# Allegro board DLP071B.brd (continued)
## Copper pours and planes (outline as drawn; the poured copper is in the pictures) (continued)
SWNODE_P3P3V on TOP (solid shape): 160.26,56.39 160.28,56.29 160.31,56.2 160.31,55.63 160.37,55.48 160.52,55.42 160.78,55.42 160.78,53.85 160.4,53.47 160.4,52.54 160.14,52.1 160.4,51.65 160.4,43.05 154.18,43.05 154.18,51.69 156.32,51.69 156.33,51.66 156.52,51.44 156.8,51.36 157.16,51.5 157.3,51.86 157.3,51.92 157.29,52 159.89,54.61 159.89,55.46 159.95,55.54 159.97,55.63 159.97,56.2 160.01,56.29 160.02,56.39 160.02,57.19 160.11,57.28 160.26,57.28
SWNODE_P5V on TOP (solid shape): 157.87,78.46 157.97,78.45 158.06,78.46 158.17,78.49 163.45,78.49 163.45,74.96 162.57,74.08 162.56,74.08 162.28,73.9 162.18,73.59 162.21,73.42 162.29,73.27 162.31,73.25 162.31,73.18 161.93,73.18 161.78,73.12 161.72,72.97 161.72,72.44 158.7,69.42 158.61,69.42 158.47,69.36 158.41,69.22 158.41,69.13 158.38,69.1 158.38,66.24 158.01,66.24 157.87,66.18 157.81,66.04 157.81,65.47 157.77,65.38 157.76,65.28 157.76,64.39 157.57,64.39 157.5,64.42 157.47,64.5 157.47,64.52 157.47,65.16 157.49,65.22 157.49,65.28 157.49,66.07 157.48,66.18 157.43,66.27 157.43,70.49 157.47,70.5 157.86,71 157.47,71.49 157.43,71.5 157.43,78.49 157.77,78.49
N16830232 on TOP (solid shape): outline of 315 points within 138.31,50.38 156.34,62.36
N16830232 on BOTTOM: 149.22,65.02 152.4,65.02 152.53,64.9 152.53,62.1 151.38,60.96 149.86,60.96 149.73,60.83 148.97,60.83 148.49,60.35 148.21,60.35 147.96,60.6 147.96,62.74 149.22,64.01
N16832566 on TOP: 168.3,68.02 169.62,68.02 170.66,66.98 170.66,64.95 171.09,64.52 173.05,64.52 173.53,65 173.53,68.76 172.75,69.55 168.76,69.55 168.3,69.09
N17060101 on TOP (solid shape): outline of 205 points within 138.53,99.54 157.61,115.06
N17234365 on TOP: 84.76,97.96 84.76,97.12 85.3,96.58 86.06,96.58 86.51,97.03 86.51,97.45 87,97.94 94.96,97.94 95.97,96.93 97.84,96.93 98.14,97.23 98.14,99.45 97.78,99.82 86.62,99.82
N17234365 on BOTTOM: 82.65,97.55 82.65,96.07 82.42,95.84 82.42,95.07 81.91,94.57 81.24,94.57 81.06,94.39 81.06,92.37 81.24,92.19 82.74,92.19 82.99,92.45 82.99,94.62 83.78,95.42 85.98,95.42 86.03,95.47 86.03,97.56 85.78,97.8 82.9,97.8
N17234365 on BOTTOM: 96.23,97.2 96.23,95.48 96.29,95.42 97.27,95.42 97.35,95.5 97.35,96.71 97.58,96.94 97.58,97.6 97.43,97.75 96.79,97.75
N18269160 on TOP: 172.82,82.35 181.69,82.35 182.27,82.93 183.9,82.93 183.9,86.54 180.57,86.54 180.39,86.36 180.39,84.48 180.31,84.4 166.47,84.4 166.47,82.83 172.34,82.83

Small or netless copper shapes (teardrops, artwork), in the pictures only: 191 on TOP

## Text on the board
BOTTOM: L08_BOTTOM
Ref Des/Assembly Bottom: ASSEMBLY_BOTTOM
Board Geometry/Soldermask Bottom: SOLDERMASK_BOTTOM
Ref Des/Silkscreen Bottom: * | APR-2023 | 305-PD-23-0338 | SILKSCREEN_BOTTOM
TOP: L01_TOP
Ref Des/Assembly Top: 2 | 1 | 119 | 120 | ASSEMBLY_TOP
Board Geometry/Soldermask Top: SOLDERMASK_TOP
Ref Des/Silkscreen Top: 1 | BALLAST | PB_DONGLE | 10 | LED_EN | JTAG_BS | SPI_CTRL | LMP_HOT | I2C_1 | MAN_RST | I2C_2 | D_BLK | 3D_TOG | CWI2 | CWI1 | CW1_MD | FO | CW2_MD | FAN4 | FAN1 | FAN5 | FAN2 | FAN6 | FAN3 | 5VFAN | LP_BYP | PWM_DRV | SPI_DRV | SM_PIC | I2C_0 | HOLD_BL | I2C_CLK | I2C_DA | L2F_SENS | KEY_PD | RS-232_1 | RS-232_0 | TEST_I/F | A | FRONTEND_I/F | FE_P1P2V | COMP_SENS | DSP_P1P8V | FAN6_EN | NOT FCC APPROVED FOR RESALE. | DLPC4430EVM | FORMATTER BOARD | DLP071 REV B | FOR EVALUATION ONLY. | SILKSCREEN_TOP | TEXAS INSTRUMENTS
L02_GND1: L02_GND1
L03_SIG1: L03_SIG1
L04_GND2: L04_GND2
L05_SIG2: L05_SIG2
L06_GND3: L06_GND3
L07_PWR: L07_PWR
DISPLAY_BOTTOM: PASTE_TOP
DISPLAY_TOP: PASTE_BOTTOM
User.11: FAB | LAYER STACK: | LAYER 1 - PRIMARY SIDE - 0.5oz+ plating START - 50 OHMS +/-10% - .0076 WIDTH | LAYER 2 - GND1 - 1 oz | LAYER 3 - SIGNAL1 - 1oz - 50 OHMS +/-10% - .0061 WIDTH | LAYER 7 - PWR  - 2oz | LAYER 8 - SECONDARY SIDE - 0.5oz+ plating START - 50 OHMS +/-10% - .0076 WIDTH | LAYER 4 - GND2 - 1 oz | LAYER 5 - SIGNAL2 - 1oz - 50 OHMS +/-10% - .0061 WIDTH | LAYER 6 - GND3 - 2oz | 2. APPLY LPI SOLDERMASK. | COLOR: GREEN. | CONFORM TO IPC-SM-840, CLASS H. CURRENT REV. | SOLDERMASK SHALL BE COMPATIBLE WITH SAC305 OR | EQUIVALENT SOLDER ALLOY AND SOLDER FLOAT BATH | TEMPERATURE OF 288 C. | 1. GENERAL PLATING :  ENIG | 3. BOARD MATERIAL SHALL BE IT-180A | OR EQUIVALENT, RoHS COMPLIANT AND LEAD FREE | ASSEMBLY CAPABLE.  BOARD MATERIAL SHALL | MEET OR EXCEED IPC-4101B. RoHS CERTIFICATE OF | CONFORMANCE SHALL BE DELIVERED WITH EACH LOT. | 8. ALL HOLES IN DRILL CHART ARE FINISHED HOLE SIZES (FHS) | 1. ALL DIMENSIONS ARE IN INCHES UNLESS | OTHERWISE NOTED. | DIELECTRIC (7.087 mil) | DIELECTRIC (4.512 mil) | DIELECTRIC (7.582 mil) | DIFFERENTIAL 100 OHMS +/-10% - .004125 WIDTH/.00588 SPACE | DIFFERENTIAL 100 OHMS +/-10% - .00425 WIDTH/.00475 SPACE | SOLDERMASK SHALL | SEE NOTE-6 | 10. NEED OVAL SLOT AS MENTIONED DIMENSION IN THE DRILL TABLE | 6. MARKED REGION DRILLS NEED TO BE SOLDERMASK PLUGGING ON BOTTOM SIDE | 4. APPLY LPI SILKSCREEN OR EQUIVALENT PER THE ARTWORK. | COLOR: WHITE. CLIP SILKSCREEN ON NO MASK AREA | 7. FABRICATION VENDOR IS ALLOWED TO INCREASE SOLDERMASK | COMPONENT PADS BY A MAXIMUM 1 MIL ON EACH SIDE OVER | THE COPPER PAD IN ORDER TO MEET TOOLING REQUIREMENTS | WHILE MAINTAINING WEBBING BETWEEN ADJACENT PADS. | 8. DEBURR ALL SHARP EDGES | 9. REMOVE UNUSED PADS IN ALL INNER LAYERS | SEE NOTE- 10
User.12: C76 | R24 | R23 | R25 | R22 | C73 | R29 | R28 | R27 | R26 | R17 | C19 | C15 | C26 | R7 | R8 | R9 | R30 | R21 | R31 | C75 | C3 | L2 | C4 | A | AA | 1 | 26 | FID | U10 | U9 | C74 | C27 | C28 | ASY1 | R56 | R55 | U1 | C9 | U6 | C11 | U2 | 40 | U5 | K | J500 | U17 | C20 | C13 | C25 | C14 | C6 | L3 | C5 | C17 | C16 | R6 | R10 | C89 | R15 | R44 | U14 | C94 | C10 | C12 | C18 | C93 | C82 | C83 | C85 | LIBRA# DLP-30285-03
User.24: FIGURE | FINISHED_SIZE | 9.0 | 12.0 | 14.0 | 20.0 | 28.0 | 35.0 | 36.0 | 38.0 | 40.0 | 42.0 | 45.0 | 50.0 | 90.0 | 157.0 | 25.98 | 60.0 | 92.5 | 94.0 | 120.0 | 118.11x39.37 | 137.795x39.37 | DRILL CHART: TOP to BOTTOM | ALL UNITS ARE IN MILS | TOLERANCE_DRILL | +3.0/-3.0 | +2.0/-2.0 | +2.0/-0.0 | PLATED | NON-PLATED | QTY | 541 | 2228 | 48 | 14 | 64 | 5 | 4 | 22 | 46 | 6 | 20 | 2 | 1
User.26: JOB NAME: | PAC NUMBER: | CUSTOMER NAME : | DATE: | FILM LAYER: | APR-2023 | DLPC4430_Rev2 | 305-PD-23-0338 | TEXAS INSTRUMENTS
